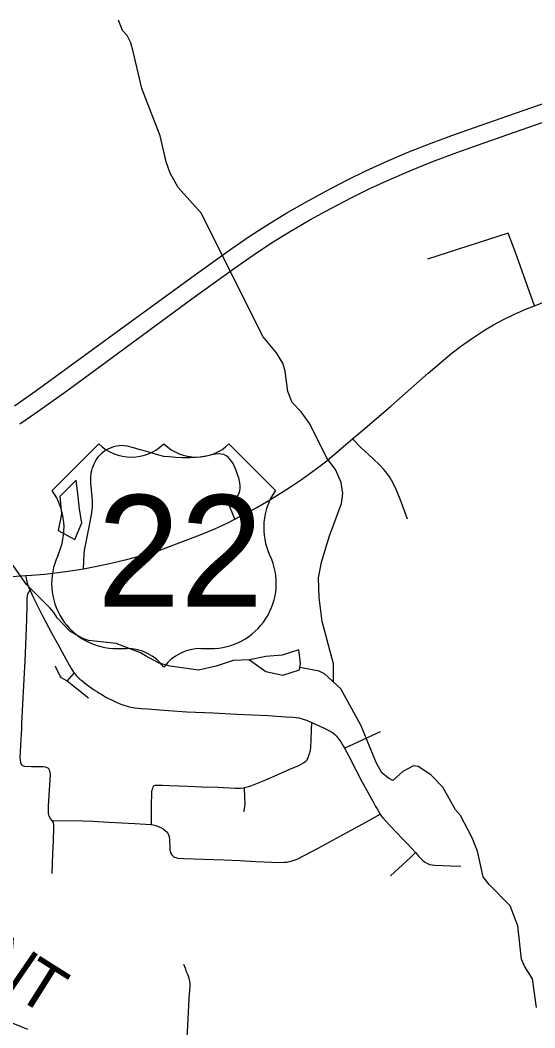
# Model space of a CAD drawing. Extents: x 0 to 34, y 0 to 22.
# Drawn here: x 3.609 to 4.217, y 15.425 to 16.615 of the extents above; entities that cross this region are included whole.
import ezdxf

# ---------------------------------------------------------------- set-up
doc = ezdxf.new("R2010")
doc.units = 0
for name, color, linetype in [('GM_X_County_Road', 7, 'Continuous'), ('GM_X_County_Road_Text', 7, 'Continuous'), ('GM_X_Interstate_Route', 7, 'Continuous'), ('GM_X_Minor_Lake', 7, 'Continuous'), ('GM_X_Minor_River', 7, 'Continuous'), ('GM_X_Township_Road', 7, 'Continuous'), ('GM_X_US_Location', 7, 'Continuous'), ('GM_X_US_Route', 7, 'Continuous'), ('GM_X_US_Shield', 7, 'Continuous')]:
    doc.layers.add(name, color=color, linetype=linetype)

msp = doc.modelspace()

# ---------------------------------------------------------------- linework, layer by layer
at = {"layer": 'GM_X_County_Road'}
msp.add_lwpolyline([(3.479, 15.5161), (3.4823, 15.5151), (3.4852, 15.514), (3.4881, 15.5127), (3.4936, 15.5096), (3.4988, 15.506), (3.5182, 15.4904), (3.5327, 15.4788), (3.5448, 15.469), (3.5592, 15.4573), (3.5714, 15.4477), (3.5788, 15.4423), (3.5865, 15.4373), (3.5945, 15.4329), (3.5972, 15.4317), (3.6001, 15.4304), (3.6172, 15.4233)], dxfattribs=at)
at = {"layer": 'GM_X_Interstate_Route'}
for points in [[(3.6019, 16.1596), (3.6272, 16.1775), (3.7277, 16.2507), (3.8157, 16.3146), (3.8586, 16.3454), (3.8791, 16.3595), (3.8999, 16.373), (3.9238, 16.3875), (3.9453, 16.3999), (3.9698, 16.4133), (3.9946, 16.4262), (4.0169, 16.4371), (4.0423, 16.4487), (4.068, 16.4596), (4.094, 16.4699), (4.1231, 16.4806), (4.1848, 16.502), (4.2493, 16.5247)], [(3.608, 16.1382), (3.626, 16.1504), (3.6638, 16.1775), (3.7039, 16.207), (3.8116, 16.2859), (3.862, 16.3223), (3.885, 16.3383), (3.9057, 16.352), (3.9269, 16.3651), (3.951, 16.3792), (3.9755, 16.3928), (4.0003, 16.4057), (4.0226, 16.4167), (4.0453, 16.427), (4.071, 16.4381), (4.0969, 16.4485), (4.129, 16.4603), (4.1847, 16.4799), (4.258, 16.5055)]]:
    msp.add_lwpolyline(points, dxfattribs=at)
at = {"layer": 'GM_X_Minor_Lake'}
for points in [[(3.6786, 16.0376), (3.6771, 16.0527), (3.6748, 16.0717), (3.6555, 16.0527), (3.6574, 16.0315), (3.6536, 16.0125), (3.6733, 16.0019), (3.6816, 16.0216), (3.6786, 16.0376)], [(3.6786, 16.0376), (3.6771, 16.0527), (3.6748, 16.0717), (3.6555, 16.0527), (3.6574, 16.0315)], [(3.6574, 16.0315), (3.6536, 16.0125), (3.6733, 16.0019), (3.6816, 16.0216), (3.6786, 16.0376)], [(3.9397, 15.8554), (3.9378, 15.8713), (3.9181, 15.8653), (3.8988, 15.8634), (3.8795, 15.8596)], [(3.9397, 15.8554), (3.9378, 15.8713), (3.9181, 15.8653), (3.8988, 15.8634), (3.8795, 15.8596), (3.8988, 15.8459), (3.9189, 15.8417), (3.9385, 15.8478), (3.9397, 15.8554)], [(3.8795, 15.8596), (3.8988, 15.8459), (3.9189, 15.8417), (3.9385, 15.8478), (3.9397, 15.8554)]]:
    msp.add_lwpolyline(points, dxfattribs=at)
at = {"layer": 'GM_X_Minor_River'}
for points in [[(3.9788, 15.8332), (3.9789, 15.8549), (3.9655, 15.905), (3.9619, 15.9334), (3.961, 15.9566), (3.9647, 15.9748), (3.974, 16.006), (3.9882, 16.0444), (3.99, 16.0562), (3.9877, 16.0691), (3.9812, 16.0846), (3.9709, 16.0979), (3.951, 16.1384), (3.9407, 16.1524), (3.9301, 16.1637), (3.9247, 16.1766), (3.9216, 16.2005), (3.9189, 16.21), (3.9116, 16.2224), (3.8957, 16.241), (3.8582, 16.3156), (3.823, 16.3867), (3.7953, 16.4173), (3.7857, 16.4344), (3.7811, 16.4476), (3.7738, 16.4783), (3.7523, 16.5344), (3.7419, 16.578), (3.7392, 16.5882), (3.735, 16.5969), (3.7296, 16.603), (3.7247, 16.6151)], [(3.8795, 15.8596), (3.8601, 15.8588), (3.8401, 15.8523), (3.8193, 15.8476), (3.7857, 15.8523), (3.7728, 15.8557), (3.7568, 15.8643), (3.7508, 15.8681), (3.722, 15.879), (3.6894, 15.8826), (3.6815, 15.8852), (3.6674, 15.8935), (3.6522, 15.9093), (3.6484, 15.9154), (3.6438, 15.9211), (3.6161, 15.9486), (3.5681, 16.0163)], [(4.2186, 15.4492), (4.2139, 15.483), (4.2043, 15.4977), (4.2009, 15.506), (4.1965, 15.5455), (4.1877, 15.569), (4.1626, 15.5943), (4.1558, 15.6034), (4.1488, 15.6337), (4.1427, 15.6496), (4.1289, 15.6758), (4.1228, 15.6826), (4.1079, 15.7091), (4.0939, 15.7238), (4.0787, 15.7336), (4.0734, 15.7343), (4.0609, 15.7278), (4.0489, 15.7171), (4.0439, 15.7197), (4.036, 15.7261), (4.0291, 15.7382), (4.0115, 15.7818), (3.9874, 15.8253), (3.968, 15.8431), (3.962, 15.8461), (3.9389, 15.8506)]]:
    msp.add_lwpolyline(points, dxfattribs=at)
at = {"layer": 'GM_X_Township_Road'}
for p, q in [((4.1851, 16.3637), (4.09, 16.3327)), ((3.6641, 15.8343), (3.6725, 15.844)), ((3.9919, 15.7554), (4.0344, 15.7748))]:
    msp.add_line(p, q, dxfattribs=at)
for points in [[(4.2162, 16.2776), (4.1934, 16.3417), (4.1851, 16.3637)], [(4.0663, 16.0256), (4.063, 16.0345), (4.0577, 16.0492), (4.053, 16.0608), (4.049, 16.0692), (4.0458, 16.0746), (4.0422, 16.0798), (4.0382, 16.0846), (4.0339, 16.0891), (4.0248, 16.0977), (4.011, 16.1103), (4.0012, 16.1205)], [(3.6835, 15.9673), (3.6841, 15.9852), (3.6849, 15.9913), (3.6868, 16.0004), (3.6906, 16.0187), (3.6927, 16.0309), (3.6939, 16.0401), (3.6941, 16.0463), (3.6938, 16.0525), (3.6922, 16.068), (3.692, 16.0742), (3.6926, 16.0804), (3.6932, 16.0834), (3.6941, 16.0864), (3.6952, 16.0893), (3.6965, 16.0921), (3.6979, 16.0949), (3.6996, 16.0975), (3.7015, 16.1), (3.7035, 16.1023), (3.7057, 16.1044), (3.7082, 16.1063), (3.7108, 16.1079), (3.7135, 16.1093), (3.7164, 16.1105), (3.7194, 16.1115), (3.7224, 16.1123), (3.7254, 16.1128), (3.7285, 16.113), (3.7316, 16.1128), (3.7347, 16.1124), (3.7437, 16.1101), (3.7496, 16.1082)], [(3.8624, 16.0259), (3.86, 16.0316), (3.8565, 16.0402), (3.8564, 16.0419), (3.8574, 16.0447), (3.8595, 16.0469), (3.8619, 16.0489), (3.864, 16.0512), (3.8659, 16.0537), (3.8673, 16.0564), (3.8682, 16.0593), (3.8687, 16.0623), (3.8686, 16.0654), (3.8683, 16.0684), (3.8668, 16.0744), (3.8659, 16.0773), (3.8639, 16.0831), (3.8615, 16.0889), (3.8601, 16.0916), (3.8584, 16.0942), (3.8565, 16.0967), (3.8543, 16.0988), (3.8518, 16.1007), (3.8491, 16.102), (3.8461, 16.1027), (3.843, 16.1028), (3.8368, 16.1021), (3.8304, 16.1007), (3.8214, 16.0991), (3.8155, 16.0985), (3.8093, 16.0983), (3.8001, 16.0983), (3.7925, 16.0987), (3.7845, 16.0992), (3.7785, 16.0999), (3.7725, 16.1013), (3.7606, 16.1048), (3.7496, 16.1082)], [(3.6148, 15.9591), (3.6168, 15.9502), (3.6178, 15.9473), (3.6202, 15.9415)], [(3.6465, 15.6699), (3.6443, 15.6724), (3.6427, 15.6751), (3.642, 15.678), (3.6419, 15.6811), (3.6422, 15.6873), (3.6432, 15.7058), (3.6441, 15.7182), (3.6444, 15.7244), (3.6439, 15.7275), (3.6434, 15.7291), (3.6428, 15.7304), (3.6415, 15.7315), (3.6403, 15.7321), (3.6384, 15.7327), (3.6358, 15.7331), (3.6325, 15.7331), (3.622, 15.7333), (3.614, 15.7336), (3.6116, 15.7345), (3.6105, 15.7356), (3.6098, 15.737), (3.6092, 15.7387), (3.6088, 15.741), (3.6087, 15.7441), (3.6098, 15.7657), (3.6105, 15.778), (3.6107, 15.7842), (3.6114, 15.7997), (3.6134, 15.8368), (3.6146, 15.8584), (3.6153, 15.8769), (3.6163, 15.9076), (3.6168, 15.9229), (3.6169, 15.9319), (3.6173, 15.9348), (3.6178, 15.9372), (3.6184, 15.9391), (3.6202, 15.9415)], [(3.6202, 15.9415), (3.6242, 15.933), (3.6355, 15.911), (3.6456, 15.8917), (3.6529, 15.878), (3.6606, 15.8645), (3.6665, 15.8537), (3.6696, 15.8482), (3.6725, 15.844)], [(3.6641, 15.8343), (3.6628, 15.8353), (3.6601, 15.8368), (3.6576, 15.8385), (3.6558, 15.8409), (3.6514, 15.8491), (3.6502, 15.852)], [(3.6725, 15.844), (3.6731, 15.843), (3.6751, 15.8407), (3.6771, 15.8387), (3.6792, 15.8368), (3.6814, 15.8351), (3.6865, 15.8309), (3.691, 15.8277), (3.6936, 15.8258), (3.6973, 15.8235), (3.7, 15.8217), (3.7021, 15.8204), (3.7046, 15.8189), (3.7075, 15.8171), (3.7099, 15.8157), (3.7123, 15.8145), (3.7164, 15.8123), (3.7213, 15.8101), (3.7276, 15.8074), (3.7312, 15.8061), (3.7362, 15.8045), (3.7393, 15.8038), (3.7439, 15.803), (3.7511, 15.8023), (3.759, 15.8018), (3.7683, 15.8009), (3.7838, 15.7998), (3.8055, 15.7984), (3.8365, 15.7969), (3.8644, 15.7954), (3.9016, 15.7937), (3.9224, 15.7924), (3.9317, 15.7918), (3.9378, 15.791), (3.9428, 15.7897), (3.9467, 15.7883), (3.9532, 15.7856)], [(3.6895, 15.8145), (3.67, 15.8296), (3.6641, 15.8343)], [(3.8737, 15.7087), (3.8753, 15.7091), (3.8784, 15.7099), (3.8813, 15.711), (3.8987, 15.7179), (3.9158, 15.7255), (3.9272, 15.7304), (3.9379, 15.735), (3.9405, 15.7363), (3.9432, 15.7378), (3.9451, 15.739), (3.9462, 15.74), (3.9472, 15.7411), (3.9478, 15.742), (3.9484, 15.7433), (3.9498, 15.7467), (3.9508, 15.7498), (3.9515, 15.7529), (3.9519, 15.7561), (3.9526, 15.7655), (3.9529, 15.7765), (3.9532, 15.7856)], [(3.9532, 15.7856), (3.9668, 15.7793), (3.9723, 15.7767), (3.9776, 15.7737), (3.9799, 15.7719), (3.9821, 15.7698), (3.9841, 15.7676), (3.9876, 15.7626), (3.9908, 15.7573), (3.9919, 15.7554)], [(3.9919, 15.7554), (3.9967, 15.7465), (4.0053, 15.7299), (4.0124, 15.7161), (4.0198, 15.7024), (4.0255, 15.6918), (4.0286, 15.6863), (4.0302, 15.6836), (4.0322, 15.6801), (4.0338, 15.6773)], [(3.7636, 15.6652), (3.7638, 15.6812), (3.7639, 15.6909), (3.7641, 15.6999), (3.7641, 15.7022), (3.7642, 15.7041), (3.7647, 15.7063), (3.7652, 15.7078), (3.7656, 15.7091), (3.7663, 15.7103)], [(3.7663, 15.7103), (3.767, 15.7111), (3.768, 15.7116), (3.7718, 15.7118), (3.7769, 15.7116), (3.7852, 15.7114), (3.7961, 15.7109), (3.8065, 15.7105), (3.8229, 15.7097), (3.8422, 15.7091), (3.8628, 15.7082), (3.869, 15.7081), (3.8722, 15.7084), (3.8737, 15.7087)], [(3.8729, 15.6805), (3.8737, 15.6832), (3.8741, 15.6866), (3.8743, 15.6897), (3.8742, 15.6966), (3.8737, 15.7087)], [(3.7636, 15.6652), (3.7659, 15.6649), (3.7689, 15.664), (3.7718, 15.6629), (3.7747, 15.6616), (3.7774, 15.66), (3.7799, 15.6582), (3.7821, 15.656), (3.7837, 15.6534), (3.7847, 15.6505), (3.7852, 15.6474), (3.7856, 15.638), (3.7856, 15.6344), (3.7861, 15.6327), (3.7867, 15.6311), (3.7874, 15.6297), (3.7884, 15.6284), (3.7896, 15.6274), (3.7908, 15.6266), (3.7926, 15.626), (3.7943, 15.6255), (3.8014, 15.6252), (3.8496, 15.6233), (3.8683, 15.6225), (3.8869, 15.6215), (3.9055, 15.6206), (3.9148, 15.6204), (3.9209, 15.6205), (3.924, 15.6208), (3.927, 15.6213), (3.93, 15.6221), (3.9358, 15.6243), (3.9441, 15.6284), (3.9605, 15.6372), (3.9823, 15.6492), (4.0177, 15.6682), (4.0338, 15.6773)], [(4.0338, 15.6773), (4.0352, 15.6753), (4.0372, 15.6729), (4.0414, 15.6682), (4.0456, 15.6637), (4.0606, 15.648), (4.0649, 15.6435), (4.0712, 15.6367), (4.0756, 15.6319)], [(3.6464, 15.6071), (3.6472, 15.6304), (3.648, 15.6458), (3.6485, 15.6613), (3.6484, 15.6644), (3.6478, 15.6674), (3.6465, 15.6699)], [(3.6465, 15.6699), (3.6826, 15.6694), (3.6946, 15.6691), (3.7132, 15.668), (3.7287, 15.6673), (3.7442, 15.6664), (3.7629, 15.6653), (3.7636, 15.6652)], [(4.0462, 15.6046), (4.0509, 15.609), (4.065, 15.6218), (4.0701, 15.6266), (4.0756, 15.6319)], [(4.0756, 15.6319), (4.0796, 15.6275), (4.084, 15.623), (4.0865, 15.621), (4.0892, 15.6193), (4.0922, 15.6181), (4.0953, 15.6175), (4.0985, 15.6171), (4.1169, 15.6163), (4.1293, 15.6159)], [(3.803, 15.3565), (3.8035, 15.3698), (3.8054, 15.406), (3.8066, 15.4278), (3.8076, 15.4435), (3.8084, 15.4595), (3.8095, 15.4744), (3.8096, 15.4773), (3.8092, 15.4803), (3.8084, 15.4831), (3.8074, 15.486), (3.8063, 15.4886), (3.8052, 15.4913), (3.8042, 15.4942), (3.8031, 15.4971), (3.8018, 15.4999)]]:
    msp.add_lwpolyline(points, dxfattribs=at)
at = {"layer": 'GM_X_US_Route'}
for points in [[(4.2162, 16.2776), (4.2272, 16.2819), (4.2562, 16.293), (4.2597, 16.2943)], [(4.0012, 16.1205), (4.0017, 16.1209), (4.0159, 16.133), (4.0464, 16.1594), (4.0908, 16.1982), (4.1192, 16.2223), (4.129, 16.2298), (4.1417, 16.2387), (4.1573, 16.2489), (4.1679, 16.2553), (4.1788, 16.2611), (4.1927, 16.2679), (4.2069, 16.2741), (4.2162, 16.2776)], [(3.8624, 16.0259), (3.8635, 16.0265), (3.8773, 16.0338), (3.8882, 16.0396), (3.9017, 16.0474), (3.9149, 16.0555), (3.9279, 16.0639), (3.9408, 16.0726), (3.9585, 16.0853), (3.9708, 16.0948), (3.9852, 16.1067), (4.0012, 16.1205)], [(3.6835, 15.9673), (3.6993, 15.9702), (3.7175, 15.9741), (3.7356, 15.9784), (3.755, 15.9837), (3.7727, 15.9889), (3.7903, 15.9955), (3.808, 16.002), (3.8232, 16.0081), (3.8385, 16.0145), (3.8538, 16.0216), (3.8624, 16.0259)], [(3.6148, 15.9591), (3.6221, 15.9596), (3.6378, 15.961), (3.6624, 15.9641), (3.6809, 15.9668), (3.6835, 15.9673)], [(3.4315, 15.9506), (3.5054, 15.9537), (3.578, 15.9566), (3.6148, 15.9591)]]:
    msp.add_lwpolyline(points, dxfattribs=at)
at = {"layer": 'GM_X_US_Shield'}
for p, q in [((3.7015, 16.1147), (3.6465, 16.0598)), ((3.9102, 16.0598), (3.8553, 16.1147)), ((3.7234, 15.873), (3.7344, 15.873)), ((3.8223, 15.873), (3.8333, 15.873))]:
    msp.add_line(p, q, dxfattribs=at)
for centre, radius, start, end in [((3.7399, 16.1539), 0.0549, 225.573, 314.427), ((3.8168, 16.1539), 0.0549, 225.573, 314.427), ((3.5835, 16.0157), 0.0769, 334.5471, 35.0009), ((3.9732, 16.0157), 0.0769, 144.9991, 205.4529), ((3.7226, 15.9499), 0.0769, 154.8319, 270.6383), ((3.8342, 15.9499), 0.0769, 269.3617, 25.1681), ((3.7344, 15.8181), 0.0549, 36.8699, 90), ((3.8223, 15.8181), 0.0549, 90, 143.1301)]:
    msp.add_arc(centre, radius, start, end, dxfattribs=at)

# ---------------------------------------------------------------- texts
at = {"layer": 'GM_X_County_Road_Text'}
for s, rotation, p in [('N', 325.5431, (3.5572, 15.4925)), ('T', 327.7784, (3.6004, 15.4628))]:
    msp.add_text(s, height=0.0568, rotation=rotation, dxfattribs=at).set_placement(p)
at = {"layer": 'GM_X_US_Location'}
for s in ['0', '/']:
    msp.add_text(s, height=0.000189, dxfattribs=at).set_placement((3.7783, 15.9873))
msp.add_text('22', height=0.000189, rotation=0, dxfattribs=at).set_placement((3.7392, 15.9481))
at = {"layer": 'GM_X_US_Shield'}
msp.add_text('22', height=0.13184, dxfattribs=at).set_placement((3.6996, 15.9224))

doc.saveas('drawing.dxf')
